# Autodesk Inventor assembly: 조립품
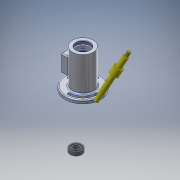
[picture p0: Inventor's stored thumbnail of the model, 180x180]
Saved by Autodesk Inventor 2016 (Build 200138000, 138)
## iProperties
Created: 2017-05
Part Number: 조립품
Material: 일반
Document SubType Name: Assembly
Designer: USER
Author: USER
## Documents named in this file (5)
- C:\Users\USER\Desktop\470508V1010\조립품.iam
- C:\Users\USER\Desktop\470508V1010\본체.ipt
- C:\Users\USER\Desktop\470508V1010\베어링 15 x 35 x 11.ipt
- C:\Users\USER\Desktop\470508V1010\축.ipt
- C:\Users\USER\Desktop\470508V1010\멈춤링 35x1.6.ipt
